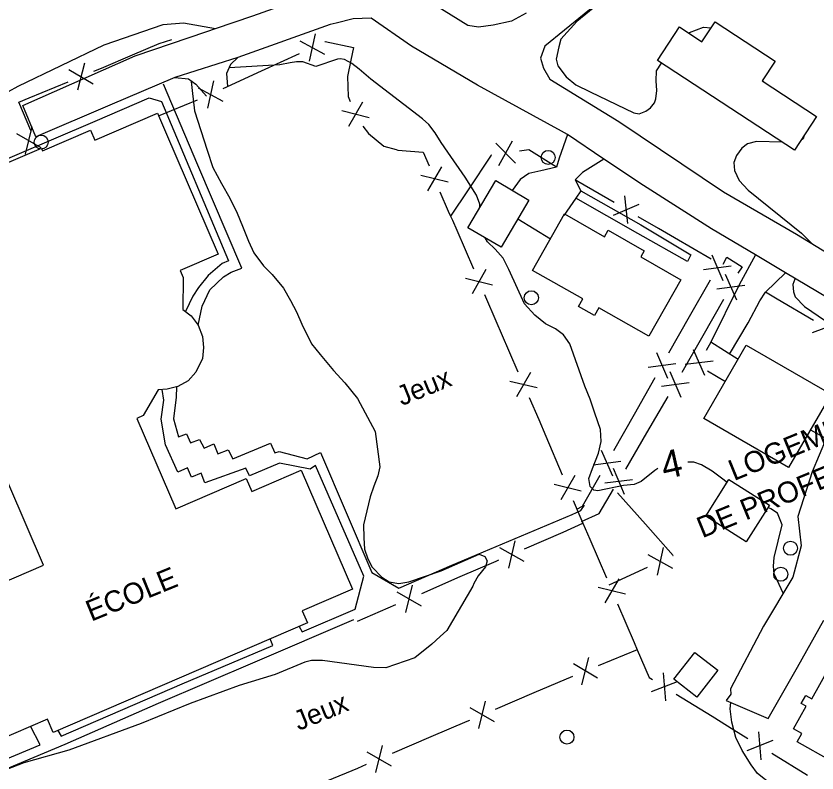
# Model space of a CAD drawing. Extents: x 362852 to 366875, y 5563573 to 5566479.
# Drawn here: x 363611.7 to 363726, y 5564807.4 to 5564915.4 of the extents above; entities that cross this region are included whole.
import ezdxf

# ---------------------------------------------------------------- set-up
doc = ezdxf.new("R2010")
doc.units = 0
for name, color, linetype in [('Niveau 19', 7, 'Continuous'), ('Niveau 2', 7, 'Continuous'), ('Niveau 21', 7, 'Continuous'), ('Niveau 22', 7, 'Continuous'), ('Niveau 31', 7, 'Continuous'), ('Niveau 36', 7, 'Continuous'), ('Niveau 37', 7, 'Continuous'), ('Niveau 56', 7, 'Continuous')]:
    doc.layers.add(name, color=color, linetype=linetype)

msp = doc.modelspace()

# ---------------------------------------------------------------- linework, layer by layer
at = {"layer": 'Niveau 19'}
msp.add_line((363683.29, 5564886.44), (363687.96, 5564883.59), dxfattribs=at)
for points in [[(363643.32, 5564909.46), (363642.25, 5564908.44), (363641.71, 5564907.18), (363641.82, 5564905.29)], [(363634.34, 5564906.59), (363636.29, 5564906.41), (363637.3, 5564905.64), (363638.83, 5564903.92)], [(363690.36, 5564898.45), (363689.18, 5564895.07), (363688.8, 5564893.81), (363686.55, 5564893.26), (363684.83, 5564892.89), (363683.63, 5564892.02), (363682.49, 5564890.48)], [(363695.58, 5564894.95), (363692.5, 5564893.02), (363691.45, 5564892.01), (363692.27, 5564890.44), (363691.55, 5564889.39), (363689.83, 5564886.88)], [(363717.2, 5564881.27), (363714.89, 5564877), (363710.85, 5564868.84)], [(363713.51, 5564867.13), (363716.17, 5564871.58), (363717.82, 5564874.71), (363718.63, 5564875.95), (363721.47, 5564878.74)], [(363725.06, 5564856.34), (363727.28, 5564855.11), (363725.31, 5564850.35), (363723.25, 5564843.95), (363723.71, 5564839.79), (363722.55, 5564835.32), (363718.33, 5564828.31), (363713.64, 5564819.37), (363713.69, 5564818.64), (363713, 5564817.73), (363719.04, 5564815.16), (363723.21, 5564822.48), (363726.94, 5564829.18)]]:
    msp.add_lwpolyline(points, dxfattribs=at)
at = {"layer": 'Niveau 2'}
for points in [[(363699.94, 5564921.34), (363691.69, 5564914.56), (363689.44, 5564912.05)], [(363707.68, 5564912.92), (363707.77, 5564913), (363709.78, 5564913.75), (363710.86, 5564913.69)], [(363689.44, 5564912.05), (363689.13, 5564910.98), (363688.76, 5564909.2), (363688.98, 5564908.23), (363690.19, 5564906.68), (363691.54, 5564905.56), (363693.59, 5564904.54), (363699.84, 5564901.54), (363700.58, 5564901.42), (363701.56, 5564901.77), (363702.24, 5564902.24), (363702.8, 5564902.97), (363703, 5564903.55), (363703.13, 5564904.73), (363703.04, 5564906.13), (363703.08, 5564907.53), (363703.8, 5564908.65)], [(363677.87, 5564888.05), (363677.84, 5564888.5), (363677.36, 5564889.79), (363675.78, 5564892.38), (363673.28, 5564895.95), (363672.33, 5564897.3), (363671.5, 5564898.7), (363670.57, 5564899.87), (363669.67, 5564900.68), (363662.29, 5564906.34), (363660.63, 5564907.76), (363659.6, 5564908.58), (363658.56, 5564909.14), (363657.94, 5564909.26), (363657.53, 5564909.21), (363654.47, 5564908.17), (363652.57, 5564908.82), (363651.7, 5564908.82), (363650.76, 5564908.68), (363649.32, 5564908.39), (363642.06, 5564907.97), (363642.05, 5564907.97)], [(363636.67, 5564906.12), (363636.64, 5564906), (363636.79, 5564904.75), (363637.14, 5564901.84), (363638.94, 5564896.22), (363639.73, 5564893.74), (363641, 5564891.46), (363642.18, 5564889.39), (363643.22, 5564887.21), (363643.98, 5564885.4), (363644.82, 5564883.25), (363645.59, 5564881.58), (363646.99, 5564879.73), (363648.2, 5564878.49), (363649.82, 5564876.55), (363650.82, 5564874.78), (363651.69, 5564873.14), (363652.43, 5564871.39), (363653.84, 5564868.61), (363655.06, 5564867.06), (363656.95, 5564864.79), (363658.61, 5564863.05), (363660.38, 5564860.79), (363662.91, 5564856.11), (363663.6, 5564851.03), (363663.31, 5564849.78), (363662.75, 5564848.29), (363662.21, 5564846.75), (363661.25, 5564842.79), (363661.29, 5564840.93), (363661.41, 5564839.29), (363661.86, 5564837.92), (363662.48, 5564836.74), (363663.88, 5564835.33), (363664.92, 5564834.65), (363666.28, 5564834.4), (363667.74, 5564834.64), (363672.33, 5564836.19), (363677.75, 5564838.6), (363678.58, 5564838.26), (363678.9, 5564837.64), (363678.69, 5564836.8), (363677.63, 5564835.48), (363677.01, 5564834.41), (363676.86, 5564834.03), (363673.14, 5564827.72), (363672.2, 5564826.83), (363671.02, 5564825.77)], [(363718.2, 5564906.15), (363718.43, 5564905.91)], [(363724.15, 5564898.31), (363724.02, 5564897.85), (363723.73, 5564897.67)], [(363721.02, 5564897.37), (363717.36, 5564897.46), (363716.07, 5564897.11), (363715.26, 5564896.52), (363714.52, 5564895.46), (363714.11, 5564894.48), (363714.22, 5564893.33), (363714.9, 5564891.87), (363716.15, 5564890.52), (363723.79, 5564884.39), (363725.25, 5564882.89)], [(363703.25, 5564850.81), (363702.85, 5564850.51), (363700.89, 5564848.94), (363699.88, 5564848.51), (363698.38, 5564848.38), (363694.69, 5564847.64), (363694.15, 5564847.73), (363693.62, 5564848.26), (363693.41, 5564849.36), (363693.92, 5564850.82), (363694.81, 5564853.01), (363695.18, 5564854.66), (363695.08, 5564856.37), (363694.28, 5564858.72), (363693.59, 5564860.68), (363692.86, 5564862.56), (363690.7, 5564868.59), (363689.78, 5564869.89), (363688.68, 5564870.74), (363687.25, 5564871.45), (363685.73, 5564872.69), (363684.24, 5564874.31), (363682, 5564879.18), (363681.21, 5564880.79), (363680.03, 5564882.1), (363678.96, 5564883.16), (363678.6, 5564883.71)], [(363722.86, 5564877.92), (363722.8, 5564877.82), (363722.54, 5564877.08), (363722.63, 5564875.99), (363722.86, 5564875.28), (363724.19, 5564873.9), (363733.04, 5564867.89), (363733.92, 5564866.82), (363734.26, 5564866.42)], [(363754.44, 5564853.14), (363754.66, 5564852.67), (363754.98, 5564850.68), (363754.94, 5564849.54), (363747.95, 5564830.7), (363745.24, 5564821.57), (363740.04, 5564810.45), (363736.2, 5564805.03), (363735.06, 5564804.17), (363734.06, 5564803.57), (363732.79, 5564803.16), (363731.89, 5564803.09), (363724.98, 5564803.63), (363723.2, 5564804), (363721.74, 5564804.64), (363719.56, 5564805.66), (363717.5, 5564807.3), (363716.61, 5564808.55), (363715.32, 5564810.57), (363714.41, 5564812.44), (363713.81, 5564814.62), (363713.57, 5564816.52), (363713.7, 5564817.43)], [(363713.15, 5564848.79), (363712.36, 5564849.44), (363711, 5564850.43), (363709.51, 5564851.31), (363708.4, 5564851.72), (363707.57, 5564851.72)], [(363721.17, 5564833.03), (363720.6, 5564834.28), (363719.85, 5564835.78), (363719.76, 5564836.87), (363719.87, 5564838.1), (363721.03, 5564842.77), (363720.34, 5564844.42), (363719.38, 5564845.07), (363718.98, 5564845.26)], [(363671.02, 5564825.77), (363668.6, 5564823.82), (363664.45, 5564822.39), (363662.7, 5564822.4), (363655.41, 5564823.4), (363653.83, 5564823.43), (363652.89, 5564823.16), (363648.62, 5564821.43), (363643.48, 5564819.83), (363636.49, 5564817.27), (363629.52, 5564814.41), (363619.17, 5564810.63), (363612.76, 5564808.81), (363608.18, 5564807.07), (363608.11, 5564807.06)]]:
    msp.add_lwpolyline(points, dxfattribs=at)
at = {"layer": 'Niveau 21'}
for points in [[(363732.29, 5564946.7), (363727.17, 5564942.61), (363720.1, 5564937.33), (363713.76, 5564932.26), (363712.04, 5564930.52), (363696.51, 5564918.73), (363692.74, 5564915.64), (363687.12, 5564911.05), (363686.52, 5564909.36), (363686.94, 5564907.91), (363687.85, 5564906.36), (363697.68, 5564900.33), (363712.65, 5564890.26), (363723.06, 5564884.22), (363730.37, 5564879.76)], [(363662.35, 5564915.07), (363659.77, 5564914.95), (363657.37, 5564914.36), (363656.49, 5564914.14), (363643.32, 5564909.46), (363634.34, 5564906.59), (363625.06, 5564902.65), (363614.48, 5564898.12), (363612.6, 5564902.58), (363628.67, 5564909.67), (363638.9, 5564913.16), (363640.11, 5564913.57), (363645.46, 5564915.4), (363650.69, 5564917.26), (363651.02, 5564918.12), (363651.17, 5564919.41), (363650.86, 5564921.5)], [(363684.47, 5564915.74), (363682.39, 5564914.6), (363679.76, 5564914.03), (363677.68, 5564913.78), (363676.14, 5564914.01), (363668.02, 5564919.11)], [(363727.56, 5564875.13), (363721.47, 5564878.74), (363717.2, 5564881.27), (363710.93, 5564884.98), (363701.21, 5564891.19), (363695.58, 5564894.95), (363690.36, 5564898.45), (363689.51, 5564898.91), (363677.54, 5564905.48), (363668.08, 5564911.07), (363662.35, 5564915.07)]]:
    msp.add_lwpolyline(points, dxfattribs=at)
at = {"layer": 'Niveau 22'}
for points in [[(363582.04, 5564884.9), (363583.9, 5564884.54), (363586.39, 5564884.87), (363588.32, 5564885.86), (363589.89, 5564887.25), (363593.57, 5564891.73), (363597.6, 5564895.67), (363605.03, 5564901.55), (363611.97, 5564905.37), (363624.25, 5564911.25), (363632.65, 5564914.15), (363635.56, 5564914.37), (363640.11, 5564913.57)], [(363637.66, 5564871.24), (363638.22, 5564873.96), (363639.3, 5564876.29), (363641.26, 5564878.17), (363642.38, 5564878.81), (363643.89, 5564879.38), (363637.6, 5564894.09), (363632.69, 5564905.65)], [(363598.15, 5564884.12), (363596.06, 5564888.86), (363605.54, 5564892.94), (363622.97, 5564900.38), (363630.67, 5564903.7), (363632.41, 5564903.16), (363641.96, 5564880.43), (363641.06, 5564880.05), (363639.09, 5564878.35), (363637.68, 5564876.63), (363636.9, 5564875.37), (363635.86, 5564873.2)], [(363692.27, 5564890.44), (363700.82, 5564885.58), (363707.99, 5564881.28), (363707.52, 5564880.33), (363700.4, 5564884.34), (363691.55, 5564889.39)], [(363712.58, 5564879.98), (363713.11, 5564880.95), (363715.31, 5564879.57), (363714.69, 5564878.68)], [(363652.06, 5564828.28), (363652.51, 5564827.5), (363660.08, 5564830.74), (363661.29, 5564835.44), (363654.41, 5564851.23), (363653.63, 5564850.71), (363649.27, 5564851.57), (363644.97, 5564849.76), (363644.45, 5564850.86), (363638.58, 5564848.77), (363638.08, 5564850.12), (363636.68, 5564849.59), (363636.12, 5564850.92), (363634.76, 5564850.29), (363633, 5564854.17), (363632.39, 5564857.85), (363632.75, 5564860.57), (363632.52, 5564862.06)], [(363634.54, 5564862.46), (363634.51, 5564860.99), (363634.13, 5564857.89), (363634.85, 5564855.31), (363635.97, 5564855.77), (363636.56, 5564854.48), (363637.86, 5564854.96), (363638.5, 5564853.73), (363639.88, 5564854.31), (363640.48, 5564852.88), (363641.91, 5564853.48), (363642.58, 5564852.2), (363647.96, 5564854.44), (363648.61, 5564853.02), (363649.22, 5564853.22), (363653.19, 5564852.21), (363655.11, 5564853.1), (363662.42, 5564835.99), (363666.3, 5564833.75), (363673.85, 5564837), (363691.04, 5564844.23), (363692.29, 5564844.82), (363692.78, 5564845.59)], [(363692.38, 5564843.25), (363694.91, 5564844.37), (363696.95, 5564847.88)], [(363659.83, 5564829.22), (363645.76, 5564823.18), (363631.94, 5564817.3), (363618.63, 5564811.44), (363607.32, 5564806.73), (363611.99, 5564795.76), (363610.92, 5564795.18), (363605.16, 5564808.45), (363601.49, 5564817.34), (363601.49, 5564817.34), (363601.42, 5564817.5), (363602.58, 5564817.86), (363605.44, 5564810.76), (363605.44, 5564810.76), (363609.54, 5564809.04), (363615.11, 5564811.38), (363613.7, 5564814.03)], [(363617.62, 5564813.44), (363618.09, 5564812.63), (363635.38, 5564820.08), (363648.33, 5564825.56), (363647.94, 5564826.5)]]:
    msp.add_lwpolyline(points, dxfattribs=at)
at = {"layer": 'Niveau 31'}
for points in [[(363722.78, 5564896.22), (363703.22, 5564909.03), (363706.35, 5564913.8), (363709.56, 5564911.69), (363711.43, 5564914.55), (363720.02, 5564908.92), (363718.16, 5564906.09), (363725.92, 5564901.01), (363722.78, 5564896.22)], [(363606.02, 5564892.54), (363615.27, 5564896.52), (363615.44, 5564896.12), (363622.29, 5564899.07), (363622.91, 5564897.63), (363631.85, 5564901.49), (363633, 5564898.83), (363640.52, 5564881.38), (363635.09, 5564879.04), (363635.53, 5564878.04), (363635.46, 5564873.5), (363636.65, 5564872.61), (363637.66, 5564871.24), (363638.27, 5564869.63), (363638.42, 5564868.09), (363638.29, 5564866.48), (363637.3, 5564864.57), (363636.21, 5564863.31), (363634.75, 5564862.51), (363633.24, 5564862.13), (363631.93, 5564862.01), (363629.79, 5564858.35)], [(363684.85, 5564889.09), (363680.89, 5564882.36), (363676.16, 5564885.15), (363680.12, 5564891.88), (363684.85, 5564889.09)], [(363689.96, 5564887.12), (363695.67, 5564883.88), (363696.19, 5564884.79), (363701.32, 5564881.88), (363700.82, 5564881), (363706.56, 5564877.74), (363701.99, 5564869.69), (363694.86, 5564873.73), (363694.24, 5564872.63), (363691.94, 5564873.93), (363692.54, 5564875), (363685.39, 5564879.05), (363689.96, 5564887.12)], [(363605.41, 5564832.66), (363615.55, 5564837.03), (363595.71, 5564883.07)], [(363721.94, 5564850.94), (363709.85, 5564857.93), (363715.9, 5564868.38), (363727.99, 5564861.39), (363721.94, 5564850.94)], [(363629.79, 5564858.35), (363628.89, 5564857.96), (363634.45, 5564845.05), (363644.49, 5564849.38), (363645.29, 5564847.51), (363652.35, 5564850.56), (363659.66, 5564833.59), (363652.5, 5564830.5), (363653.24, 5564828.79), (363616.95, 5564813.15), (363616.12, 5564815.07), (363606.4, 5564810.88)], [(363715.9, 5564840.37), (363710.13, 5564844), (363713.42, 5564849.22), (363719.19, 5564845.59), (363715.9, 5564840.37)], [(363711.81, 5564822.03), (363708.83, 5564818.21), (363705.57, 5564820.75), (363708.55, 5564824.58), (363711.81, 5564822.03)], [(363728.07, 5564809.08), (363723.15, 5564811.83), (363723.81, 5564813.01), (363722.65, 5564813.66), (363724.45, 5564816.89), (363723.72, 5564817.29), (363724.37, 5564818.45), (363725.26, 5564817.95), (363727.79, 5564822.46)]]:
    msp.add_lwpolyline(points, dxfattribs=at)
at = {"layer": 'Niveau 36'}
for centre in [(363615.24, 5564897.37), (363687.61, 5564895.18), (363685.21, 5564875.17), (363722.21, 5564839.43), (363720.81, 5564835.72), (363690.3, 5564812.49)]:
    msp.add_circle(centre, 1, dxfattribs=at)
at = {"layer": 'Niveau 37'}
for p, q in [((363654.35, 5564912.82), (363653.51, 5564908.91)), ((363652.17, 5564911.81), (363655.69, 5564909.91)), ((363646.67, 5564907.52), (363652.12, 5564910.03)), ((363621.43, 5564908.65), (363620.43, 5564904.77)), ((363619.21, 5564907.73), (363622.65, 5564905.69)), ((363641.22, 5564905.02), (363646.67, 5564907.52)), ((363613.54, 5564903.67), (363619.09, 5564905.95)), ((363637.64, 5564905.13), (363641.16, 5564903.22)), ((363639.82, 5564906.13), (363638.98, 5564902.22)), ((363632, 5564901.14), (363637.56, 5564903.4)), ((363661.11, 5564903.06), (363659.09, 5564899.61)), ((363662.04, 5564900.85), (363658.16, 5564901.82)), ((363613.91, 5564899.55), (363612.96, 5564895.66)), ((363611.7, 5564898.61), (363615.17, 5564896.61)), ((363682.94, 5564894.37), (363680.12, 5564897.21)), ((363680.56, 5564894.04), (363682.5, 5564897.54)), ((363672.39, 5564893.86), (363670.38, 5564890.41)), ((363673.32, 5564891.65), (363669.44, 5564892.62)), ((363691.85, 5564891.77), (363691.45, 5564892.01)), ((363697.03, 5564888.74), (363691.85, 5564891.77)), ((363676.19, 5564890.55), (363673.68, 5564886.79)), ((363698.99, 5564885.74), (363698.54, 5564889.72)), ((363696.92, 5564886.96), (363700.61, 5564888.5)), ((363674.56, 5564884.79), (363676.94, 5564879.28)), ((363710.86, 5564880.69), (363705.67, 5564883.7)), ((363710.96, 5564881.29), (363712.56, 5564877.63)), ((363678.73, 5564879.19), (363676.74, 5564875.71)), ((363709.77, 5564879.21), (363713.74, 5564879.71)), ((363679.68, 5564876.98), (363675.79, 5564877.92)), ((363707.81, 5564872.51), (363710.77, 5564877.73)), ((363712.89, 5564878.54), (363714.48, 5564874.87)), ((363711.7, 5564876.46), (363715.67, 5564876.96)), ((363720.3, 5564874.97), (363718.63, 5564875.95)), ((363709.72, 5564869.76), (363712.69, 5564874.97)), ((363725.48, 5564871.94), (363720.3, 5564874.97)), ((363704.85, 5564867.29), (363707.81, 5564872.51)), ((363725.33, 5564870.22), (363729.08, 5564871.63)), ((363680.92, 5564870.11), (363683.3, 5564864.6)), ((363706.75, 5564864.55), (363709.72, 5564869.76)), ((363709.97, 5564864.06), (363708.37, 5564867.72)), ((363703.06, 5564867.37), (363704.67, 5564863.71)), ((363701.88, 5564865.28), (363705.85, 5564865.8)), ((363711.15, 5564866.14), (363707.19, 5564865.64)), ((363685.08, 5564864.51), (363683.1, 5564861.03)), ((363704.96, 5564864.64), (363706.55, 5564860.97)), ((363710.34, 5564864.73), (363712.91, 5564863.23)), ((363686.04, 5564862.3), (363682.15, 5564863.23)), ((363699.93, 5564858.58), (363702.88, 5564863.81)), ((363703.77, 5564862.56), (363707.74, 5564863.06)), ((363701.72, 5564855.91), (363704.76, 5564861.08)), ((363696.98, 5564853.36), (363699.93, 5564858.58)), ((363687.27, 5564855.42), (363689.62, 5564849.9)), ((363698.68, 5564850.73), (363701.72, 5564855.91)), ((363695.2, 5564853.44), (363696.8, 5564849.78)), ((363694.02, 5564851.35), (363697.98, 5564851.87)), ((363696.9, 5564850.84), (363698.45, 5564847.16)), ((363691.4, 5564849.79), (363689.4, 5564846.33)), ((363695.69, 5564848.77), (363699.66, 5564849.23)), ((363692.34, 5564847.59), (363688.46, 5564848.54)), ((363701.5, 5564842.88), (363697.51, 5564847.36)), ((363689.75, 5564841.75), (363692.58, 5564842.99)), ((363684.24, 5564839.36), (363689.75, 5564841.75)), ((363682.87, 5564840.5), (363681.95, 5564836.61)), ((363693.56, 5564840.71), (363695.93, 5564835.2)), ((363680.67, 5564839.54), (363684.15, 5564837.57)), ((363704.03, 5564839.52), (363703.19, 5564835.61)), ((363701.85, 5564838.52), (363705.37, 5564836.61)), ((363696.34, 5564834.23), (363701.79, 5564836.73)), ((363669.56, 5564833), (363675.07, 5564835.38)), ((363697.71, 5564835.09), (363695.71, 5564831.63)), ((363665.99, 5564833.2), (363669.46, 5564831.21)), ((363668.19, 5564834.15), (363667.26, 5564830.26)), ((363698.65, 5564832.89), (363694.77, 5564833.83)), ((363660.38, 5564829.04), (363665.89, 5564831.42)), ((363697.5, 5564831.52), (363699.87, 5564826.01)), ((363700.32, 5564824.96), (363694.77, 5564822.67)), ((363694.65, 5564820.89), (363691.21, 5564822.93)), ((363692.43, 5564819.97), (363693.43, 5564823.85)), ((363691.08, 5564821.14), (363685.56, 5564818.79)), ((363704.01, 5564821.65), (363704.37, 5564817.67)), ((363706.05, 5564820.39), (363702.32, 5564818.93)), ((363685.56, 5564818.79), (363680.04, 5564816.44)), ((363705.89, 5564818.61), (363711, 5564815.46)), ((363677.72, 5564813.72), (363678.68, 5564817.6)), ((363679.93, 5564814.66), (363676.47, 5564816.66)), ((363670.84, 5564812.51), (363665.33, 5564810.14)), ((363717.62, 5564813.25), (363717.99, 5564809.27)), ((363719.66, 5564812), (363715.95, 5564810.53)), ((363665.23, 5564808.36), (363661.76, 5564810.36)), ((363663.02, 5564807.42), (363663.96, 5564811.3)), ((363719.52, 5564810.22), (363724.63, 5564807.08))]:
    msp.add_line(p, q, dxfattribs=at)
for points in [[(363628.3, 5564909.83), (363632.07, 5564911.44), (363633.89, 5564912)], [(363655.75, 5564911.7), (363655.79, 5564911.72), (363659.82, 5564910.87), (363659.45, 5564909.07)], [(363622.78, 5564907.48), (363623.86, 5564907.92), (363628.3, 5564909.83)], [(363659.45, 5564909.07), (363658.97, 5564906.71), (363659.04, 5564903.87), (363659.33, 5564903.18)], [(363613.75, 5564899.02), (363612.04, 5564903.05), (363613.54, 5564903.67)], [(363661.16, 5564899.65), (363661.96, 5564898.59), (363664.15, 5564896.8), (363665.92, 5564896.3)], [(363665.92, 5564896.3), (363666.16, 5564896.23), (363669.79, 5564895.92), (363670.61, 5564893.97)], [(363688.8, 5564893.81), (363684.85, 5564896.25), (363683.51, 5564896.06)], [(363679.54, 5564895.51), (363679.49, 5564895.5), (363676.19, 5564890.55)], [(363672.17, 5564890.29), (363673.33, 5564887.53), (363673.68, 5564886.79), (363673.94, 5564886.23), (363674.56, 5564884.79)], [(363705.67, 5564883.7), (363703.36, 5564885.03), (363700.48, 5564886.72)], [(363678.53, 5564875.61), (363680.29, 5564871.55), (363680.92, 5564870.11)], [(363714.72, 5564866.35), (363710.85, 5564868.84), (363710.16, 5564867.62)], [(363684.89, 5564860.93), (363686.26, 5564857.78), (363687.27, 5564855.42)], [(363691.71, 5564845.02), (363692.5, 5564845.42), (363695.02, 5564849.87)], [(363691.19, 5564846.22), (363691.6, 5564845.26), (363691.71, 5564845.02), (363692.58, 5564842.99), (363693.56, 5564840.71)], [(363705.43, 5564838.4), (363705.46, 5564838.42), (363701.5, 5564842.88)], [(363675.07, 5564835.38), (363680.21, 5564837.6), (363680.58, 5564837.76)], [(363699.87, 5564826.01), (363700.32, 5564824.96), (363702.02, 5564821), (363702.49, 5564820.71)], [(363676.36, 5564814.87), (363675.98, 5564814.71), (363670.84, 5564812.51)], [(363711, 5564815.46), (363714.13, 5564813.52), (363716.11, 5564812.31)], [(363661.65, 5564808.57), (363660.4, 5564808.03), (363656.12, 5564806.24)]]:
    msp.add_lwpolyline(points, dxfattribs=at)

# ---------------------------------------------------------------- texts
at = {"layer": 'Niveau 2'}
msp.add_text('4', height=3.93, rotation=12.6834, dxfattribs=at).set_placement((363704.21, 5564849.23))
at = {"layer": 'Niveau 31'}
for s, p in [('LOGEMENTS', (363714.13, 5564849)), ('DE PROFESSEURS', (363709.61, 5564840.84)), ('ÉCOLE', (363622.39, 5564828.94))]:
    msp.add_text(s, height=3, rotation=22.2287, dxfattribs=at).set_placement(p)
at = {"layer": 'Niveau 56'}
for p in [(363666.71, 5564859.7), (363651.99, 5564813.36)]:
    msp.add_text('Jeux', height=2.81, rotation=22.09, dxfattribs=at).set_placement(p)

doc.saveas('drawing.dxf')
